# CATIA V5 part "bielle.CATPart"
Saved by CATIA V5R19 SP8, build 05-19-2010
Part number: bielle
Bounding box of the stored display mesh (mm): x 58 to 71, y 22.366 to 335.561, z 18.039 to 75.79
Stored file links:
  G:\EU_thinkMotion\CFAO_2010\MMS_groupe3\MMS_groupe3\A reprendre\amenand\amenand\bielle.CATPart
  F:\thinkmotion CFAO v12.1\essuie_glace.CATProduct
  G:\EU_thinkMotion\CFAO_2010\MMS_groupe3\MMS_groupe3\A reprendre\amenand\amenand\squelette_bielle.CATPart
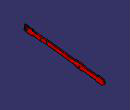
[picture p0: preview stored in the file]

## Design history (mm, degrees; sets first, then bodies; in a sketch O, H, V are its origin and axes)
Set1
  Plane1: linked copy from another document
  Line1: linked copy from another document
  Plane2 to Plane4: linked copy from another document
  Point1 to Point4: linked copy from another document
Body1 (main body)
  Sketch1 on Plane1, origin (76, 0, 0), H (0, 1, 0), V (0, 0, 1)
    line L1 (55.7505, 72.0476) -> (23.9831, 75.8985)
    point P2 (23.9831, 75.8985)
    line L2 (54.2016, 51.0817) -> (22.4341, 54.9325)
    reference projected line E1 (30.629, 64.516) -> (315.748, 29.954) from Line1
    line L3 (55.7505, 72.0476) -> (58.3562, 67.7025)
    point P5 (58.3562, 67.7025)
    line L4 (54.2016, 51.0817) -> (56.0687, 54.8846)
    line L5 (56.0687, 54.8846) -> (211.773, 36.0102)
    line L6 (211.773, 36.0102) -> (230.7451, 29.6811)
    line L7 (230.7451, 29.6811) -> (244.6434, 27.9964)
    line L8 (244.6434, 27.9964) -> (251.3561, 30.2047)
    line L9 (251.3561, 30.2047) -> (302.9782, 23.9471)
    line L10 (302.9782, 23.9471) -> (306.9323, 20.4458)
    line L11 (306.9323, 20.4458) -> (326.787, 18.039)
    line L12 (326.787, 18.039) -> (334.7189, 24.1287)
    line L13 (334.7189, 24.1287) -> (335.5613, 31.0779)
    point P15 (335.5613, 31.0779)
    line L14 (335.5613, 31.0779) -> (329.3141, 38.8864)
    line L15 (329.3141, 38.8864) -> (309.4594, 41.2932)
    line L16 (309.4594, 41.2932) -> (306.0601, 38.6833)
    line L17 (306.0601, 38.6833) -> (254.4379, 44.9409)
    line L18 (254.4379, 44.9409) -> (246.1413, 48.9686)
    line L19 (246.1413, 48.9686) -> (232.243, 50.6533)
    line L20 (232.243, 50.6533) -> (212.3082, 49.0405)
    line L21 (212.3082, 49.0405) -> (58.3562, 67.7025)
    point P23 (58.3562, 67.7025)
    line L22 (23.9831, 75.8985) -> (20.9469, 71.7336)
    point P24 (23.9831, 75.8985)
    point P25 (20.9469, 71.7336)
    line L23 (20.9469, 71.7336) -> (19.5028, 59.8208)
    point P26 (20.9469, 71.7336)
    line L24 (19.5028, 59.8208) -> (22.4341, 54.9325)
    reference projected line E2 (30.629, 64.516) -> (315.748, 29.954) from Line1
    reference projected line E3 (30.629, 64.516) -> (315.748, 29.954) from Line1
    reference projected line E4 (30.629, 64.516) -> (315.748, 29.954) from Line1
    reference projected line E5 (30.629, 64.516) -> (315.748, 29.954) from Line1
    reference projected line E6 (30.629, 64.516) -> (315.748, 29.954) from Line1
    reference projected line E7 (30.629, 64.516) -> (315.748, 29.954) from Line1
    distance L1 L2 = 21
    distance L1 E1 = 10.5
    length L1 = 32
    length L2 = 32
    distance L5 L21 = 13
    distance L5 E2 = 6.5
    length L6 = 20
    length L20 = 20
    distance L7 L19 = 21
    length L7 = 14
    length L19 = 14
    distance L7 E3 = 10.5
    distance L9 L17 = 15
    length L9 = 52
    length L17 = 52
    distance L9 E4 = 7.5
    length L11 = 20
    length L15 = 20
    distance L11 E5 = 10.5
    distance L11 L15 = 21
    length L23 = 12
    distance P25 E6 = 6
    length L13 = 7
    distance P15 E7 = 3.5
    length L12 = 10
    length L14 = 10
    coincidence: P26 L22, P2 P24, P25 P26, P5 P23
    perpendicularity: L23 L2
    parallelism: L24 L3, L9 L17, L13 L23, L12 L16
  Sketch2 on Plane2, origin (0, 8.1509, 67.2408), H (-1, 0, 0), V (0, -0.9927, 0.1203)
    line L1 (-69.4131, -15.5792) -> (-69.4131, -80.1603)
    line L2 (-69.4131, -80.1603) -> (-67, -101.2043)
    line L3 (-67, -101.2043) -> (-67, -345.2589)
    point P4 (-67, -345.2589)
    point P5 (-62, -345.2589)
    line L4 (-62, -345.2589) -> (-62, -247.0995)
    point P6 (-62, -247.0995)
    line L5 (-69.4131, -15.5792) -> (-66.4131, -15.5792)
    line L6 (-66.4131, -15.5792) -> (-66.4131, -34.9007)
    line L7 (-66.4131, -34.9007) -> (-63.926, -66.8672)
    line L8 (-63.926, -66.8672) -> (-63.926, -77.3993)
    line L9 (-63.926, -77.3993) -> (-62, -94.1957)
    line L10 (-62, -94.1957) -> (-62, -247.0995)
    point P12 (-62, -247.0995)
    line L11 (-62, -247.0995) -> (-62, -247.0995)
    point P13 (-62, -247.0995)
    line L12 (-62, -345.2589) -> (-67, -345.2589)
    point P14 (-62, -345.2589)
    point P15 (-67, -345.2589)
    point P16 (-67, -345.2589)
    reference intersected line E1 through (-67, 0) direction (0, -1) from Plane3
    reference intersected line E2 through (-62, 0) direction (0, -1) from Plane4
    reference intersected line E3 through (-62, 0) direction (0, -1) from Plane4
    distance L6 L1 = 3
    vertical: L1 V, L3 V, L6 V, L8 V, L10 V, L4 V
    horizontal: L5 H, L12 H
    parallelism: L9 L2
    coincidence: P14 L4, P5 P14, P16 L12, P15 P16, L3 E1, P4 L12, L4 E2, L10 E3, P13 P12, P12 P6, P15 P4
  SolidCombine1: FirstComponentProfile Sketch1, FirstComponentDirection Sketch1, SecondComponentProfile Sketch2, SecondComponentDirection Sketch2
  Sketch3 on face of SolidCombine1 from Sketch2.L6, origin (66.4131, 37.2576, 53.1592), H (0, 1, 0), V (0, 0, -1)
    point P1 (-6.6286, -11.3568)
    reference projected point E1 (-6.6286, -11.3568) from Point1
    coincidence: P1 E1
  Hole1: placed by Sketch3, at (66.4131, 30.629, 64.516) direction (1, 0, 0), diameter 12, through (limit type 6)
  Sketch4 on Plane3, origin (67, 222.8275, 0.0123), H (0, 1, 0), V (0, 0, 1)
    circle A1 centre (17.456, 39.0895) radius 2
    point P1 (17.456, 39.0895)
    reference projected point E1 (17.456, 39.0895) from Point2
    radius A1 = 2
    coincidence: P1 E1
  Pad1: profile Sketch4, direction (1, 0, 0), length 4
  Sketch5 on Plane4, origin (62, 227.9085, 0.0122), H (0, 1, 0), V (0, 0, 1)
    circle A1 centre (91.1014, 29.5464) radius 2
    point P1 (91.1014, 29.5464)
    reference projected point E1 (91.1014, 29.5464) from Point4
    radius A1 = 2
    coincidence: P1 E1
  Pad2: profile Sketch5, direction (-1, 0, 0), length 4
